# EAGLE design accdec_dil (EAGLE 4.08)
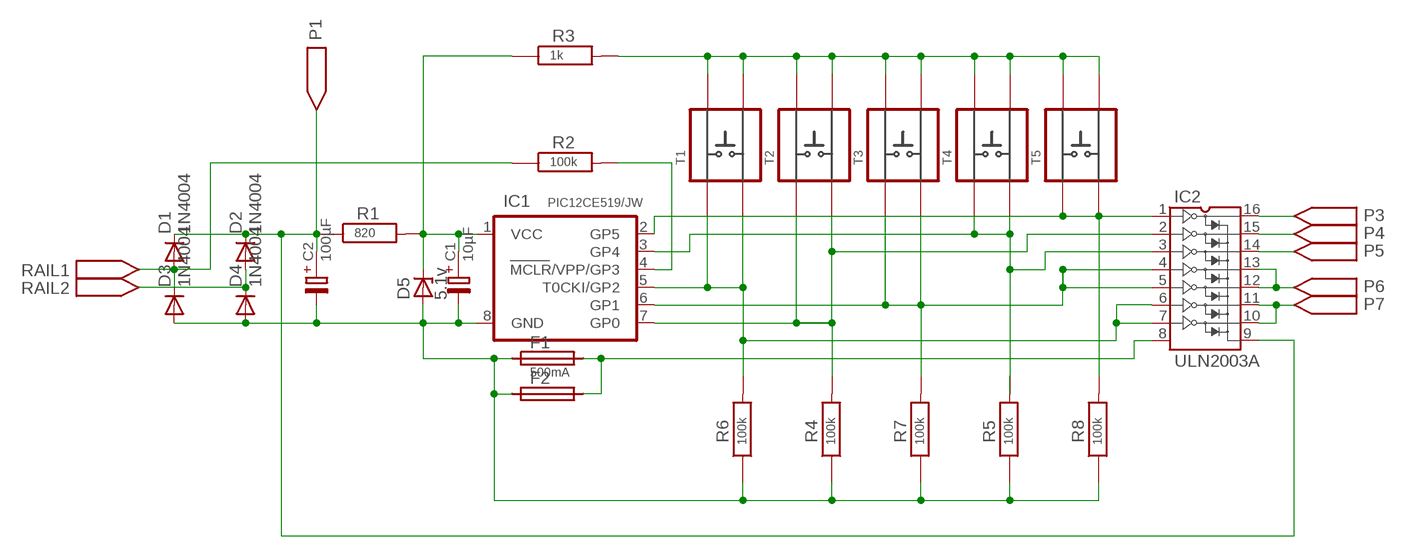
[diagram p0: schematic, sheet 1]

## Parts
C1  10µF  TT2,5-3  [TT2,5-3]
C2  100µF  TT5,0-10  [TT5,0-10]
D1  1N4004  [DO41-10]
D2  1N4004  [DO41-10]
D3  1N4004  [DO41-10]
D4  1N4004  [DO41-10]
D5  5.1v  ZPD  [DO35Z10]
F1  500mA  FUSE  [1210]
F2  FUSE_D  [R207-7]
IC1  PIC12CE519/JW  [DIL08]
IC2  ULN2003A  ULN2001AD  [DIL16]
P1  PORT_S  [CON_1]
P3  PORT_S  [CON_1]
P4  PORT_S  [CON_1]
P5  PORT_S  [CON_1]
P6  PORT_S  [CON_1]
P7  PORT_S  [CON_1]
R1  820  R-207-10  [R207-10]
R2  100k  R-207-10  [R207-10]
R3  1k  R-207-10  [R207-10]
R4  100k  R-207-10  [R207-10]
R5  100k  R-207-10  [R207-10]
R6  100k  R-207-10  [R207-10]
R7  100k  R-207-10  [R207-10]
R8  100k  R-207-10  [R207-10]
RAIL1  PORT_S  [CON_1]
RAIL2  PORT_S  [CON_1]
T1  TASTER  TASTER13G4402  [TASTER]
T2  TASTER  TASTER13G4402  [TASTER]
T3  TASTER  TASTER13G4402  [TASTER]
T4  TASTER  TASTER13G4402  [TASTER]
T5  TASTER  TASTER13G4402  [TASTER]

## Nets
+: C2.+ D1.C D2.C IC2.9(COM) P1.P$1 R1.P$1
DCCIN: IC1.4(MCLR/VPP/GP3) R2.P$2
FUSE: F1.2 F2.P$2 IC2.8(GND)
GND: C1.- C2.- D3.A D4.A D5.A F1.1 F2.P$1 IC1.8(GND) R4.P$1 R5.P$1 R6.P$1 R7.P$1 R8.P$1
GP0: IC1.5(T0CKI/GP2) IC2.6(IN6) IC2.7(IN7) R6.P$2 T1.T1 T1.T2
GP1: IC1.6(GP1) IC2.4(IN4) IC2.5(IN5) R7.P$2 T3.T1 T3.T2
GP2: IC1.2(GP5) IC2.1(IN1) R8.P$2 T5.T1 T5.T2
GP4: IC1.7(GP0) IC2.2(IN2) R4.P$2 T2.T1 T2.T2
GP5: IC1.3(GP4) IC2.3(IN3) R5.P$2 T4.T1 T4.T2
N$1: IC2.16(OUT1) P3.P$1
N$2: IC2.15(OUT2) P4.P$1
N$3: IC2.14(OUT3) P5.P$1
N$4: IC2.12(OUT5) IC2.13(OUT4) P6.P$1
N$5: IC2.10(OUT7) IC2.11(OUT6) P7.P$1
N$6: D2.A D4.C RAIL2.P$1
PROG: R3.P$2 T1.T3 T1.T4 T2.T3 T2.T4 T3.T3 T3.T4 T4.T3 T4.T4 T5.T3 T5.T4
RAIL1: D1.A D3.C R2.P$1 RAIL1.P$1
VCC: C1.+ D5.C IC1.1(VCC) R1.P$2 R3.P$1

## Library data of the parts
C1 = CAP-PAN:TT2,5-3
C2 = CAP-PAN:TT5,0-10
D1-D4 = diode:1N4004: DIODE
D5 = diode:ZPD: Z DIODE
F1 F2 = NMRA-DCC_Decoder_Parts:FUSE
IC1 = NMRA-DCC_Decoder_Parts:PIC12C*?: PIC12Cx5xx 8 bit Microchip Microcontroller with 2k byte PROM and 16 byte EEPROM
IC2 = NMRA-DCC_Decoder_Parts:UL
P1 P3-P7 RAIL1 RAIL2 = NMRA-DCC_Decoder_Parts:PORT
R1-R8 = NMRA-DCC_Decoder_Parts:R-: Resistor
T1-T5 = NMRA-DCC_Decoder_Parts:TASTER

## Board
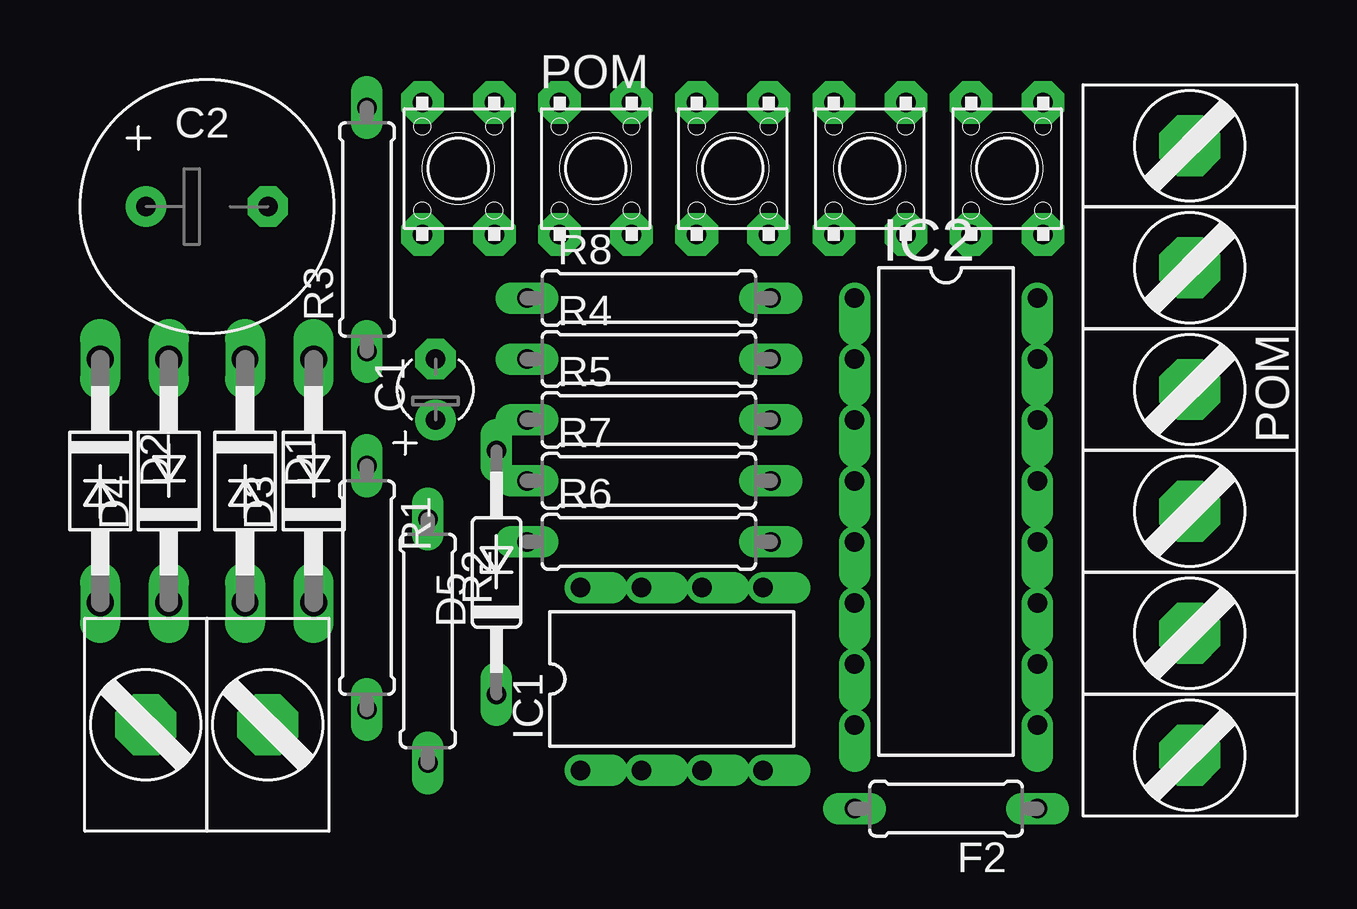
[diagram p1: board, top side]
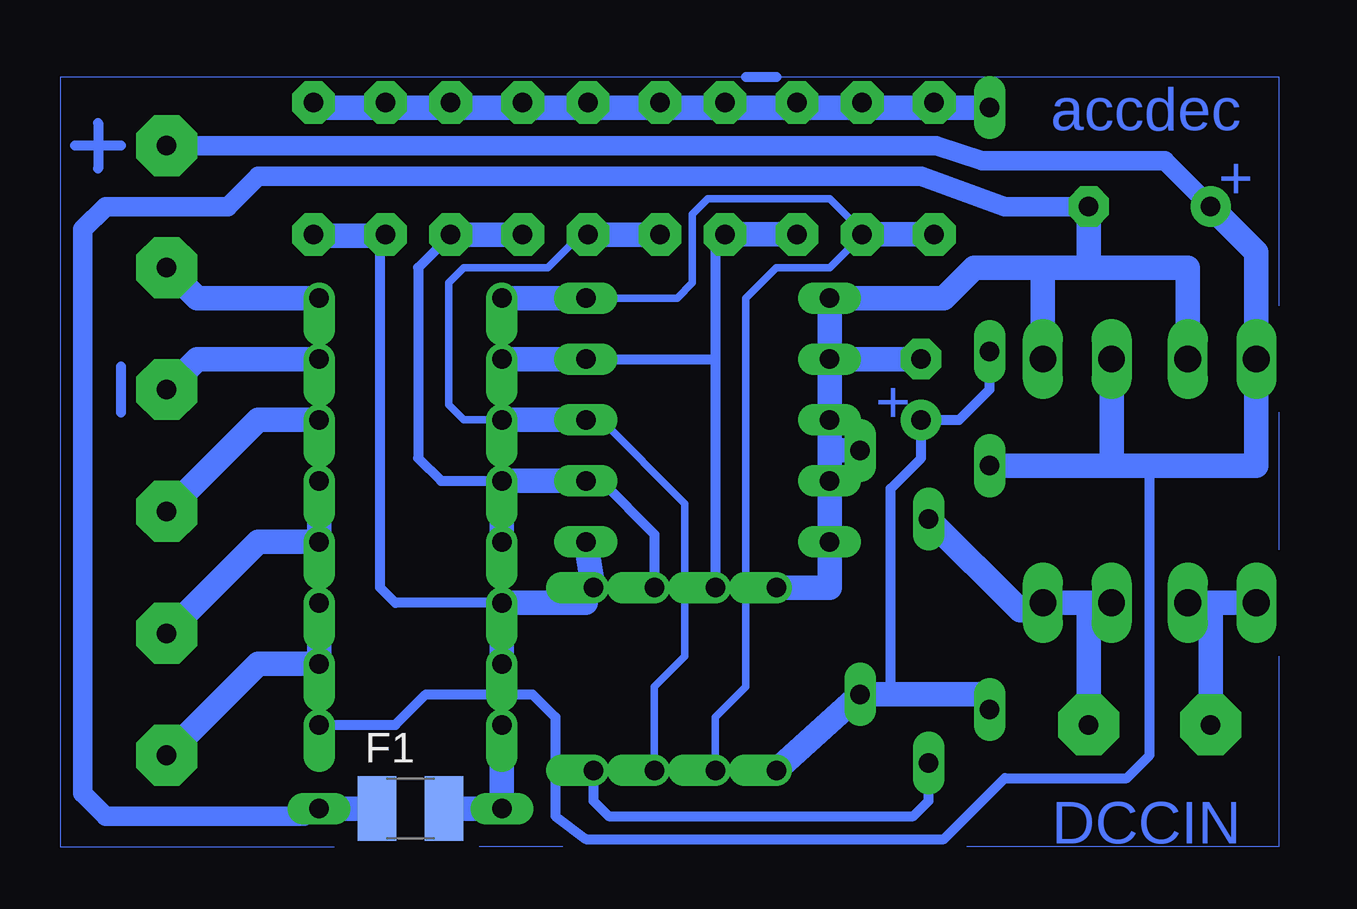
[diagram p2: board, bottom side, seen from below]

No outline drawn. Coordinates in mm, seen from the top.
Copper layers used: Bottom

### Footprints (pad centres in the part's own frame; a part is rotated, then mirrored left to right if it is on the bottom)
TT2,5-3 = drill 0.813 pad 1.676 round: + -1.27,0 | drill 0.813 pad 1.676 octagon: - 1.27,0
TT5,0-10 = drill 0.813 pad 1.676 round: + -2.54,0 | drill 0.813 pad 1.676 octagon: - 2.54,0
DO41-10 = drill 1.118 long: A 5.08,0; C -5.08,0
DO35Z10 = drill 0.813 long: A 5.08,0; C -5.08,0
1210 = smd 1.6 x 2.7: 1 -1.4,0; 2 1.4,0
R207-7 = drill 0.813 long: P$1 -3.81,0; P$2 3.81,0
DIL08 = drill 0.813 offset: 1 -3.81,-3.81; 2 -1.27,-3.81; 3 1.27,-3.81; 4 3.81,-3.81; 5 3.81,3.81; 6 1.27,3.81; 7 -1.27,3.81; 8 -3.81,3.81
DIL16 = drill 0.813 offset: 1 -8.89,-3.81; 2 -6.35,-3.81; 3 -3.81,-3.81; 4 -1.27,-3.81; 5 1.27,-3.81; 6 3.81,-3.81; 7 6.35,-3.81; 8 8.89,-3.81; 9 8.89,3.81; 10 6.35,3.81; 11 3.81,3.81; 12 1.27,3.81; 13 -1.27,3.81; 14 -3.81,3.81; 15 -6.35,3.81; 16 -8.89,3.81
CON_1 = drill 0.813 pad 2.54 octagon: P$1 0,0
R207-10 = drill 0.813 long: P$1 -5.08,0; P$2 5.08,0
TASTER = drill 0.813 pad 1.778 octagon: T1 -2.75,1.5; T2 -2.75,-1.5; T3 2.75,1.5; T4 2.75,-1.5

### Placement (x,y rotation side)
C1  43.5,31.75 90 top
C2  33.97,39.37 0 top
D1  35.56,27.94 270 top
D2  29.53,27.94 270 top
D3  38.42,27.94 90 top
D4  32.38,27.94 90 top
D5  46.04,24.13 90 top
F1  64.77,14.29 0 bottom
F2  64.77,14.29 180 top
IC1  53.34,19.68 0 top
IC2  64.77,26.67 270 top
P1  74.93,41.91 0 top
P3  74.93,36.83 0 top
P4  74.93,31.75 0 top
P5  74.93,26.67 0 top
P6  74.93,21.59 0 top
P7  74.93,16.51 0 top
R1  40.64,23.5 270 top
R2  43.18,21.27 270 top
R3  40.64,38.42 90 top
R4  52.39,33.02 0 top
R5  52.39,30.48 0 top
R6  52.39,25.4 0 top
R7  52.39,27.94 0 top
R8  52.39,35.56 0 top
RAIL1  36.51,17.78 90 top
RAIL2  31.43,17.78 270 top
T1  67.31,40.96 90 top
T2  50.16,40.96 90 top
T3  61.59,40.96 90 top
T4  55.88,40.96 90 top
T5  44.45,40.96 90 top

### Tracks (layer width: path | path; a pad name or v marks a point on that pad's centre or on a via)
+
  Bottom 0.406: IC2.9 65.41,17.78 64.14,19.05 59.69,19.05 58.74,18.1 58.74,13.97 57.47,13.02 42.55,13.02 40.01,15.56 34.92,15.56 33.97,16.51 33.97,28.57 | 29.53,28.57 29.53,37.47 33.34,41.27
  Bottom 0.813: C2.+ 33.34,41.27 40.96,41.27 42.86,41.91 P1.P$1 75.25,41.91
  Bottom 1.016: C2.+ 29.53,37.47 D2.C 29.53,28.57 33.97,28.57 35.56,28.57 | 35.56,28.57 R1.P$1 | 35.56,28.57 D1.C
DCCIN
  Bottom 0.406: IC1.4 57.15,14.61 56.52,13.97 43.81,13.97 43.18,14.61 R2.P$2
FUSE
  Bottom 1.016: F2.P$2 F1.2 F2.P$2 | IC2.8 F2.P$2
GND
  Bottom 0.406: R5.P$1 R4.P$1 | R7.P$1 R5.P$1 | R7.P$1 R5.P$1 | R7.P$1 R6.P$1 | R7.P$1 R6.P$1 | R6.P$1 47.31,29.21 | R7.P$1 R6.P$1 | R8.P$1 R4.P$1 | R4.P$1 C1.- | R4.P$1 R7.P$1 | R7.P$1 R6.P$1 | R7.P$1 R5.P$1
  Bottom 0.813: F2.P$1 69.22,13.97 77.47,13.97 78.42,14.92 78.42,38.42 77.47,39.37 72.39,39.37 71.12,40.64 43.5,40.64 40.01,39.37 C2.-
  Bottom 1.016: 47.31,29.21 D5.A | C1.- R4.P$1 | D4.A 32.38,36.83 36.51,36.83 | 38.42,36.83 D3.A | F1.1 F2.P$1 | C2.- 36.51,36.83 | 36.51,36.83 38.42,36.83 | 38.42,36.83 41.27,36.83 42.55,35.56 R8.P$1 R4.P$1 | R4.P$1 R6.P$1 47.31,23.5 IC1.8
GP0
  Bottom 0.406: 66.04,38.16 65.83,38.21 T1.T1 65.93,38.21 66.04,38.16 | 68.58,38.16 T1.T2 | IC1.5 57.47,22.86 | IC2.6 65.41,22.86 66.04,23.5 66.04,38.16
  Bottom 1.016: 66.04,38.16 68.58,38.16 | IC1.5 R6.P$2 | 57.47,22.86 IC2.6 IC2.7
GP1
  Bottom 0.406: R7.P$2 56.83,27.94 54.61,25.72 IC1.6 | 63.18,38.1 63.09,38.19 | 63.09,38.19 T3.T2 | T3.T1 63.08,38.21 63.09,38.19 | 63.18,38.21 63.18,38.1 | 63.18,38.1 64.45,36.83 64.45,28.89 63.5,27.94 61.28,27.94 60.96,28.26 IC2.4
  Bottom 1.016: IC2.5 IC2.4 R7.P$2 | T3.T1 63.18,38.21
GP2
  Bottom 0.305: IC1.2 52.07,18.1 50.8,19.37 50.8,35.56 49.53,36.83 47.31,36.83 46.04,38.1 | T5.T2 46.15,38.52 46.04,38.1 | R8.P$2 53.66,35.56 53.02,36.2 53.02,39.05 52.39,39.69 47.31,39.69 46.04,38.42 46.04,38.1
  Bottom 0.406: T5.T1 43.29,38.21 43.27,38.23 | 45.93,38.21 T5.T2 | 45.81,38.23 45.93,38.21 | 45.93,38.21 42.97,38.21 42.86,38.1 | R8.P$2 IC2.1 R8.P$2
  Bottom 1.016: 43.27,38.23 45.81,38.23 | R8.P$2 IC2.1
GP4
  Bottom 0.406: T2.T1 48.69,38.21 48.9,38.23 | 51.44,38.23 51.65,38.21 T2.T2 51.66,38.19 52.07,38.1 52.07,33.02 | R4.P$2 52.07,33.02 | 52.07,33.02 IC1.7
  Bottom 1.016: 48.9,38.23 51.44,38.23 | R4.P$2 IC2.2
GP5
  Bottom 0.305: 57.68,38.21 59.05,36.83 62.55,36.83 63.18,36.2 63.18,31.11 62.55,30.48 IC2.3 | 56.83,30.48 53.34,26.99 53.34,20.64 54.61,19.37 IC1.3
  Bottom 0.406: IC2.3 R5.P$2 56.83,30.48 | T4.T2 57.68,38.21 | 54.29,38.1 54.38,38.19 | 54.38,38.19 T4.T1 | 54.4,38.21 54.38,38.19
  Bottom 1.016: IC2.3 56.83,30.48 | T4.T2 54.4,38.21
N$1
  Bottom 1.016: IC2.16 73.66,35.56 P3.P$1
N$2
  Bottom 1.016: IC2.15 73.66,33.02 P4.P$1
N$3
  Bottom 1.016: IC2.14 71.12,30.48 P5.P$1
N$4
  Bottom 1.016: P6.P$1 71.12,25.4 IC2.12 IC2.13
N$5
  Bottom 1.016: P7.P$1 71.12,20.32 IC2.10 IC2.11
N$6
  Bottom 1.016: RAIL2.P$1 31.43,22.86 | D4.C 31.43,22.86 | 31.43,22.86 D2.A
N$7
  Bottom 0.406: 76.83,41.91 78.74,41.91
N$8
  Bottom 0.406: 77.79,42.86 77.79,40.96
N$9
  Bottom 0.406: 76.83,32.7 76.83,30.8
N$10
  Bottom 0.406: 49.53,44.77 50.8,44.77
N$11
  Bottom 0: 41.59,12.7 28.57,12.7 28.57,20.64
N$12
  Bottom 0: 28.57,25.08 28.57,30.8
N$13
  Bottom 0: 28.57,35.24 28.57,44.77 79.38,44.77 79.38,12.7 67.94,12.7
N$14
  Bottom 0: 58.42,12.7 61.91,12.7
PROG
  Bottom 0.406: 43.18,43.5 T5.T3 42.74,43.5 | 45.72,43.5 T5.T4 46.04,43.5 | 48.58,43.5 T2.T3 48.9,43.5 | 51.44,43.5 T2.T4 51.75,43.5 | 54.29,43.5 T4.T3 54.61,43.5 | 57.15,43.5 T4.T4 57.47,43.5 | 60.01,43.5 T3.T3 60.33,43.5 | 62.87,43.5 T3.T4 63.18,43.5 | 65.72,43.5 T1.T3 66.04,43.5 | 68.58,43.5 T1.T4
  Bottom 1.016: 43.18,43.5 45.72,43.5 | 46.04,43.5 48.58,43.5 | 48.9,43.5 51.44,43.5 | 51.75,43.5 54.29,43.5 | 54.61,43.5 57.15,43.5 | 57.47,43.5 60.01,43.5 | 60.33,43.5 62.87,43.5 | 63.18,43.5 65.72,43.5 | 66.04,43.5 68.58,43.5 | 42.74,43.5 R3.P$2
RAIL1
  Bottom 1.016: RAIL1.P$1 36.51,22.86 | D1.A 36.51,22.86 | 36.51,22.86 D3.C 39.37,22.54 R2.P$1
VCC
  Bottom 0.406: D5.C IC1.1 | 44.77,19.05 44.77,27.62 43.5,28.89 C1.+ 41.91,30.48 40.64,31.75 R3.P$1 | R1.P$2 40.64,19.05
  Bottom 1.016: IC1.1 D5.C 44.77,19.05 40.64,19.05

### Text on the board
Bottom: accdec | + | + | DCCIN
tPlace: POM | POM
